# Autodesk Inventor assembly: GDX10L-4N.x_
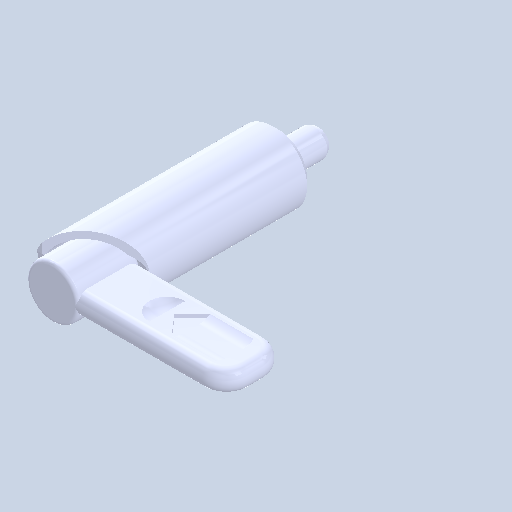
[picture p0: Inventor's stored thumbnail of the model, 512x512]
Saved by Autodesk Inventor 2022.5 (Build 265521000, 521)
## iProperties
Created: 2024-06
Part Number: GDX10L-4N.x_
Document SubType Name: Assembly
Designer: ImaoCorp
Author: ImaoCorp
Sending System: SOLIDWORKS 2022-2022290
MC: AMD64
MC_MODEL: Intel64 Family 6 Model 60 Stepping 3, GenuineIntel
OS: Windows_NT
FRU: Parasolid Version 33.1, build 260,  4-25-2022
FORMAT: text
GUISE: transmit
KEY: FILEGDX10L-4N.x_t
DATE: Wed Jun 12 09:31:09 2024
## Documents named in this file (3)
- Y:\5.更新分\2024年対応\xxxx_GDX\データ_imao品番\gdx10l-4n\GDX10L-4N.x_.iam
- Y:\5.更新分\2024年対応\xxxx_GDX\データ_imao品番\gdx10l-4n\GDX10L-4N_01.ipt
- Y:\5.更新分\2024年対応\xxxx_GDX\データ_imao品番\gdx10l-4n\GDX10L-4N_02.ipt
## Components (2 placed, 2 different names)
1. GDX10L-4N_01
2. GDX10L-4N_02
